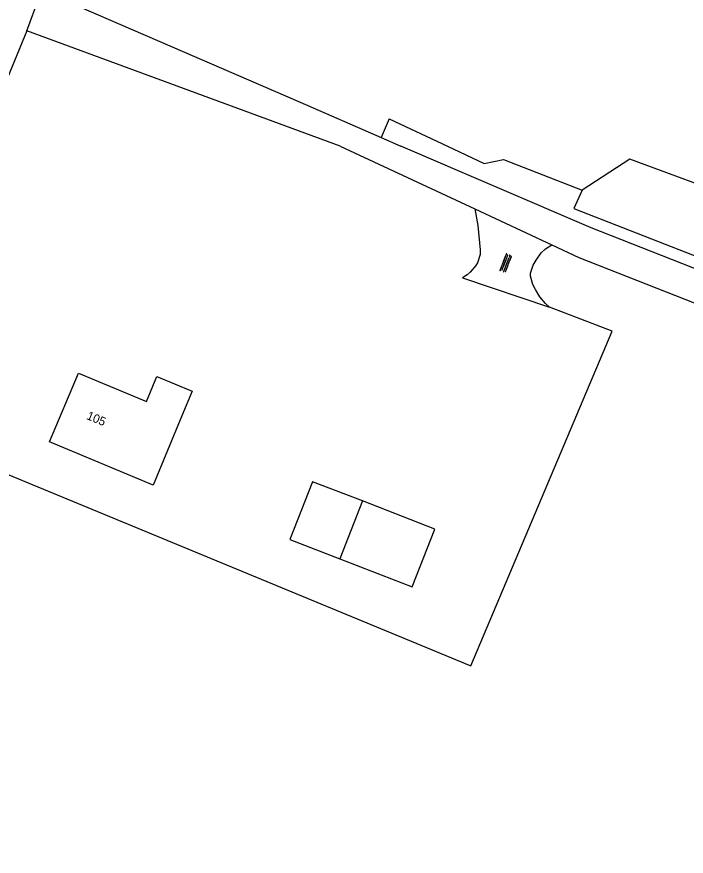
# Model space of a CAD drawing. Extents: x 130998 to 133001, y 398999 to 403002.
# Drawn here: x 131386.2 to 131463.7, y 400917.8 to 401015 of the extents above; entities that cross this region are included whole.
import ezdxf

# ---------------------------------------------------------------- set-up
doc = ezdxf.new("R2010")
doc.units = 0
for name, color, linetype in [('gg-afsc-hekwerk', 7, 'Continuous'), ('gg-anno-huisnummerreeks BGT', 7, 'Continuous'), ('gg-bbg-bijgebouw', 7, 'Continuous'), ('gg-bbg-hoofdgebouw', 7, 'Continuous'), ('gg-bbg-open loods', 7, 'Continuous'), ('gg-knt-onverhard', 7, 'Continuous'), ('gt-grn-groengrens', 7, 'Continuous'), ('gt-grn-weggrens', 7, 'Continuous'), ('gt-symb-overige verharding', 7, 'Continuous')]:
    doc.layers.add(name, color=color, linetype=linetype)

# ---------------------------------------------------------------- blocks, each defined once
blk = doc.blocks.new('gt0-OVH')
at = {"layer": 'gt-symb-overige verharding'}
for points in [[(-0.972, 0.298), (-0.967, 0.308), (-0.965, 0.319), (-0.966, 0.33), (-0.971, 0.34), (-0.978, 0.348), (-0.988, 0.353), (-0.999, 0.355), (-1.01, 0.354), (-1.02, 0.349), (-1.028, 0.342), (-1.033, 0.332), (-1.035, 0.321), (-1.034, 0.31), (-1.029, 0.3), (-1.022, 0.292), (-1.012, 0.287), (-1.001, 0.285), (-0.99, 0.286), (-0.98, 0.291)], [(-0.872, 0.106), (-0.867, 0.116), (-0.865, 0.126), (-0.866, 0.137), (-0.871, 0.147), (-0.878, 0.156), (-0.888, 0.161), (-0.899, 0.163), (-0.91, 0.162), (-0.92, 0.157), (-0.928, 0.15), (-0.933, 0.14), (-0.935, 0.129), (-0.934, 0.118), (-0.929, 0.108), (-0.922, 0.1), (-0.912, 0.095), (-0.901, 0.092), (-0.89, 0.094), (-0.88, 0.098)], [(-0.772, 0.298), (-0.767, 0.308), (-0.765, 0.319), (-0.766, 0.33), (-0.771, 0.34), (-0.778, 0.348), (-0.788, 0.353), (-0.799, 0.355), (-0.81, 0.354), (-0.82, 0.349), (-0.828, 0.342), (-0.833, 0.332), (-0.835, 0.321), (-0.834, 0.31), (-0.829, 0.3), (-0.822, 0.292), (-0.812, 0.287), (-0.801, 0.285), (-0.79, 0.286), (-0.78, 0.291)], [(-0.672, 0.106), (-0.667, 0.116), (-0.665, 0.126), (-0.666, 0.137), (-0.671, 0.147), (-0.678, 0.156), (-0.688, 0.161), (-0.699, 0.163), (-0.71, 0.162), (-0.72, 0.157), (-0.728, 0.15), (-0.733, 0.14), (-0.735, 0.129), (-0.734, 0.118), (-0.729, 0.108), (-0.722, 0.1), (-0.712, 0.095), (-0.701, 0.092), (-0.69, 0.094), (-0.68, 0.098)], [(-0.572, 0.298), (-0.567, 0.308), (-0.565, 0.319), (-0.566, 0.33), (-0.571, 0.34), (-0.578, 0.348), (-0.588, 0.353), (-0.599, 0.355), (-0.61, 0.354), (-0.62, 0.349), (-0.628, 0.342), (-0.633, 0.332), (-0.635, 0.321), (-0.634, 0.31), (-0.629, 0.3), (-0.622, 0.292), (-0.612, 0.287), (-0.601, 0.285), (-0.59, 0.286), (-0.58, 0.291)], [(-0.472, 0.106), (-0.467, 0.116), (-0.465, 0.126), (-0.466, 0.137), (-0.471, 0.147), (-0.478, 0.156), (-0.488, 0.161), (-0.499, 0.163), (-0.51, 0.162), (-0.52, 0.157), (-0.528, 0.15), (-0.533, 0.14), (-0.535, 0.129), (-0.534, 0.118), (-0.529, 0.108), (-0.522, 0.1), (-0.512, 0.095), (-0.501, 0.092), (-0.49, 0.094), (-0.48, 0.098)], [(-0.372, 0.298), (-0.367, 0.308), (-0.365, 0.319), (-0.366, 0.33), (-0.371, 0.34), (-0.378, 0.348), (-0.388, 0.353), (-0.399, 0.355), (-0.41, 0.354), (-0.42, 0.349), (-0.428, 0.342), (-0.433, 0.332), (-0.435, 0.321), (-0.434, 0.31), (-0.429, 0.3), (-0.422, 0.292), (-0.412, 0.287), (-0.401, 0.285), (-0.39, 0.286), (-0.38, 0.291)], [(-0.272, 0.106), (-0.267, 0.116), (-0.265, 0.126), (-0.266, 0.137), (-0.271, 0.147), (-0.278, 0.156), (-0.288, 0.161), (-0.299, 0.163), (-0.31, 0.162), (-0.32, 0.157), (-0.328, 0.15), (-0.333, 0.14), (-0.335, 0.129), (-0.334, 0.118), (-0.329, 0.108), (-0.322, 0.1), (-0.312, 0.095), (-0.301, 0.092), (-0.29, 0.094), (-0.28, 0.098)], [(-0.172, 0.298), (-0.167, 0.308), (-0.165, 0.319), (-0.166, 0.33), (-0.171, 0.34), (-0.178, 0.348), (-0.188, 0.353), (-0.199, 0.355), (-0.21, 0.354), (-0.22, 0.349), (-0.228, 0.342), (-0.233, 0.332), (-0.235, 0.321), (-0.234, 0.31), (-0.229, 0.3), (-0.222, 0.292), (-0.212, 0.287), (-0.201, 0.285), (-0.19, 0.286), (-0.18, 0.291)], [(-0.072, 0.106), (-0.067, 0.116), (-0.065, 0.126), (-0.066, 0.137), (-0.071, 0.147), (-0.078, 0.156), (-0.088, 0.161), (-0.099, 0.163), (-0.11, 0.162), (-0.12, 0.157), (-0.128, 0.15), (-0.133, 0.14), (-0.135, 0.129), (-0.134, 0.118), (-0.129, 0.108), (-0.122, 0.1), (-0.112, 0.095), (-0.101, 0.092), (-0.09, 0.094), (-0.08, 0.098)], [(0.028, 0.298), (0.033, 0.308), (0.035, 0.319), (0.034, 0.33), (0.029, 0.34), (0.022, 0.348), (0.012, 0.353), (0.001, 0.355), (-0.01, 0.354), (-0.02, 0.349), (-0.028, 0.342), (-0.033, 0.332), (-0.035, 0.321), (-0.034, 0.31), (-0.029, 0.3), (-0.022, 0.292), (-0.012, 0.287), (-0.001, 0.285), (0.01, 0.286), (0.02, 0.291)], [(0.128, 0.106), (0.133, 0.116), (0.135, 0.126), (0.134, 0.137), (0.129, 0.147), (0.122, 0.156), (0.112, 0.161), (0.101, 0.163), (0.09, 0.162), (0.08, 0.157), (0.072, 0.15), (0.067, 0.14), (0.065, 0.129), (0.066, 0.118), (0.071, 0.108), (0.078, 0.1), (0.088, 0.095), (0.099, 0.092), (0.11, 0.094), (0.12, 0.098)], [(0.228, 0.298), (0.233, 0.308), (0.235, 0.319), (0.234, 0.33), (0.229, 0.34), (0.222, 0.348), (0.212, 0.353), (0.201, 0.355), (0.19, 0.354), (0.18, 0.349), (0.172, 0.342), (0.167, 0.332), (0.165, 0.321), (0.166, 0.31), (0.171, 0.3), (0.178, 0.292), (0.188, 0.287), (0.199, 0.285), (0.21, 0.286), (0.22, 0.291)], [(0.328, 0.106), (0.333, 0.116), (0.335, 0.126), (0.334, 0.137), (0.329, 0.147), (0.322, 0.156), (0.312, 0.161), (0.301, 0.163), (0.29, 0.162), (0.28, 0.157), (0.272, 0.15), (0.267, 0.14), (0.265, 0.129), (0.266, 0.118), (0.271, 0.108), (0.278, 0.1), (0.288, 0.095), (0.299, 0.092), (0.31, 0.094), (0.32, 0.098)], [(0.428, 0.298), (0.433, 0.308), (0.435, 0.319), (0.434, 0.33), (0.429, 0.34), (0.422, 0.348), (0.412, 0.353), (0.401, 0.355), (0.39, 0.354), (0.38, 0.349), (0.372, 0.342), (0.367, 0.332), (0.365, 0.321), (0.366, 0.31), (0.371, 0.3), (0.378, 0.292), (0.388, 0.287), (0.399, 0.285), (0.41, 0.286), (0.42, 0.291)], [(0.528, 0.106), (0.533, 0.116), (0.535, 0.126), (0.534, 0.137), (0.529, 0.147), (0.522, 0.156), (0.512, 0.161), (0.501, 0.163), (0.49, 0.162), (0.48, 0.157), (0.472, 0.15), (0.467, 0.14), (0.465, 0.129), (0.466, 0.118), (0.471, 0.108), (0.478, 0.1), (0.488, 0.095), (0.499, 0.092), (0.51, 0.094), (0.52, 0.098)], [(0.628, 0.298), (0.633, 0.308), (0.635, 0.319), (0.634, 0.33), (0.629, 0.34), (0.622, 0.348), (0.612, 0.353), (0.601, 0.355), (0.59, 0.354), (0.58, 0.349), (0.572, 0.342), (0.567, 0.332), (0.565, 0.321), (0.566, 0.31), (0.571, 0.3), (0.578, 0.292), (0.588, 0.287), (0.599, 0.285), (0.61, 0.286), (0.62, 0.291)], [(0.728, 0.106), (0.733, 0.116), (0.735, 0.126), (0.734, 0.137), (0.729, 0.147), (0.722, 0.156), (0.712, 0.161), (0.701, 0.163), (0.69, 0.162), (0.68, 0.157), (0.672, 0.15), (0.667, 0.14), (0.665, 0.129), (0.666, 0.118), (0.671, 0.108), (0.678, 0.1), (0.688, 0.095), (0.699, 0.092), (0.71, 0.094), (0.72, 0.098)], [(0.828, 0.298), (0.833, 0.308), (0.835, 0.319), (0.834, 0.33), (0.829, 0.34), (0.822, 0.348), (0.812, 0.353), (0.801, 0.355), (0.79, 0.354), (0.78, 0.349), (0.772, 0.342), (0.767, 0.332), (0.765, 0.321), (0.766, 0.31), (0.771, 0.3), (0.778, 0.292), (0.788, 0.287), (0.799, 0.285), (0.81, 0.286), (0.82, 0.291)], [(0.928, 0.106), (0.933, 0.116), (0.935, 0.126), (0.934, 0.137), (0.929, 0.147), (0.922, 0.156), (0.912, 0.161), (0.901, 0.163), (0.89, 0.162), (0.88, 0.157), (0.872, 0.15), (0.867, 0.14), (0.865, 0.129), (0.866, 0.118), (0.871, 0.108), (0.878, 0.1), (0.888, 0.095), (0.899, 0.092), (0.91, 0.094), (0.92, 0.098)], [(1.028, 0.298), (1.033, 0.308), (1.035, 0.319), (1.034, 0.33), (1.029, 0.34), (1.022, 0.348), (1.012, 0.353), (1.001, 0.355), (0.99, 0.354), (0.98, 0.349), (0.972, 0.342), (0.967, 0.332), (0.965, 0.321), (0.966, 0.31), (0.971, 0.3), (0.978, 0.292), (0.988, 0.287), (0.999, 0.285), (1.01, 0.286), (1.02, 0.291)], [(-0.972, -0.142), (-0.967, -0.132), (-0.965, -0.121), (-0.966, -0.11), (-0.971, -0.1), (-0.978, -0.092), (-0.988, -0.087), (-0.999, -0.085), (-1.01, -0.086), (-1.02, -0.091), (-1.028, -0.098), (-1.033, -0.108), (-1.035, -0.119), (-1.034, -0.13), (-1.029, -0.14), (-1.022, -0.148), (-1.012, -0.153), (-1.001, -0.155), (-0.99, -0.154), (-0.98, -0.149)], [(-0.872, -0.334), (-0.867, -0.324), (-0.865, -0.314), (-0.866, -0.303), (-0.871, -0.293), (-0.878, -0.284), (-0.888, -0.279), (-0.899, -0.277), (-0.91, -0.278), (-0.92, -0.283), (-0.928, -0.29), (-0.933, -0.3), (-0.935, -0.311), (-0.934, -0.322), (-0.929, -0.332), (-0.922, -0.34), (-0.912, -0.345), (-0.901, -0.348), (-0.89, -0.346), (-0.88, -0.342)], [(-0.772, -0.142), (-0.767, -0.132), (-0.765, -0.121), (-0.766, -0.11), (-0.771, -0.1), (-0.778, -0.092), (-0.788, -0.087), (-0.799, -0.085), (-0.81, -0.086), (-0.82, -0.091), (-0.828, -0.098), (-0.833, -0.108), (-0.835, -0.119), (-0.834, -0.13), (-0.829, -0.14), (-0.822, -0.148), (-0.812, -0.153), (-0.801, -0.155), (-0.79, -0.154), (-0.78, -0.149)], [(-0.672, -0.334), (-0.667, -0.324), (-0.665, -0.314), (-0.666, -0.303), (-0.671, -0.293), (-0.678, -0.284), (-0.688, -0.279), (-0.699, -0.277), (-0.71, -0.278), (-0.72, -0.283), (-0.728, -0.29), (-0.733, -0.3), (-0.735, -0.311), (-0.734, -0.322), (-0.729, -0.332), (-0.722, -0.34), (-0.712, -0.345), (-0.701, -0.348), (-0.69, -0.346), (-0.68, -0.342)], [(-0.572, -0.142), (-0.567, -0.132), (-0.565, -0.121), (-0.566, -0.11), (-0.571, -0.1), (-0.578, -0.092), (-0.588, -0.087), (-0.599, -0.085), (-0.61, -0.086), (-0.62, -0.091), (-0.628, -0.098), (-0.633, -0.108), (-0.635, -0.119), (-0.634, -0.13), (-0.629, -0.14), (-0.622, -0.148), (-0.612, -0.153), (-0.601, -0.155), (-0.59, -0.154), (-0.58, -0.149)], [(-0.472, -0.334), (-0.467, -0.324), (-0.465, -0.314), (-0.466, -0.303), (-0.471, -0.293), (-0.478, -0.284), (-0.488, -0.279), (-0.499, -0.277), (-0.51, -0.278), (-0.52, -0.283), (-0.528, -0.29), (-0.533, -0.3), (-0.535, -0.311), (-0.534, -0.322), (-0.529, -0.332), (-0.522, -0.34), (-0.512, -0.345), (-0.501, -0.348), (-0.49, -0.346), (-0.48, -0.342)], [(-0.372, -0.142), (-0.367, -0.132), (-0.365, -0.121), (-0.366, -0.11), (-0.371, -0.1), (-0.378, -0.092), (-0.388, -0.087), (-0.399, -0.085), (-0.41, -0.086), (-0.42, -0.091), (-0.428, -0.098), (-0.433, -0.108), (-0.435, -0.119), (-0.434, -0.13), (-0.429, -0.14), (-0.422, -0.148), (-0.412, -0.153), (-0.401, -0.155), (-0.39, -0.154), (-0.38, -0.149)], [(-0.272, -0.334), (-0.267, -0.324), (-0.265, -0.314), (-0.266, -0.303), (-0.271, -0.293), (-0.278, -0.284), (-0.288, -0.279), (-0.299, -0.277), (-0.31, -0.278), (-0.32, -0.283), (-0.328, -0.29), (-0.333, -0.3), (-0.335, -0.311), (-0.334, -0.322), (-0.329, -0.332), (-0.322, -0.34), (-0.312, -0.345), (-0.301, -0.348), (-0.29, -0.346), (-0.28, -0.342)], [(-0.172, -0.142), (-0.167, -0.132), (-0.165, -0.121), (-0.166, -0.11), (-0.171, -0.1), (-0.178, -0.092), (-0.188, -0.087), (-0.199, -0.085), (-0.21, -0.086), (-0.22, -0.091), (-0.228, -0.098), (-0.233, -0.108), (-0.235, -0.119), (-0.234, -0.13), (-0.229, -0.14), (-0.222, -0.148), (-0.212, -0.153), (-0.201, -0.155), (-0.19, -0.154), (-0.18, -0.149)], [(-0.072, -0.334), (-0.067, -0.324), (-0.065, -0.314), (-0.066, -0.303), (-0.071, -0.293), (-0.078, -0.284), (-0.088, -0.279), (-0.099, -0.277), (-0.11, -0.278), (-0.12, -0.283), (-0.128, -0.29), (-0.133, -0.3), (-0.135, -0.311), (-0.134, -0.322), (-0.129, -0.332), (-0.122, -0.34), (-0.112, -0.345), (-0.101, -0.348), (-0.09, -0.346), (-0.08, -0.342)], [(0.028, -0.142), (0.033, -0.132), (0.035, -0.121), (0.034, -0.11), (0.029, -0.1), (0.022, -0.092), (0.012, -0.087), (0.001, -0.085), (-0.01, -0.086), (-0.02, -0.091), (-0.028, -0.098), (-0.033, -0.108), (-0.035, -0.119), (-0.034, -0.13), (-0.029, -0.14), (-0.022, -0.148), (-0.012, -0.153), (-0.001, -0.155), (0.01, -0.154), (0.02, -0.149)], [(0.128, -0.334), (0.133, -0.324), (0.135, -0.314), (0.134, -0.303), (0.129, -0.293), (0.122, -0.284), (0.112, -0.279), (0.101, -0.277), (0.09, -0.278), (0.08, -0.283), (0.072, -0.29), (0.067, -0.3), (0.065, -0.311), (0.066, -0.322), (0.071, -0.332), (0.078, -0.34), (0.088, -0.345), (0.099, -0.348), (0.11, -0.346), (0.12, -0.342)], [(0.228, -0.142), (0.233, -0.132), (0.235, -0.121), (0.234, -0.11), (0.229, -0.1), (0.222, -0.092), (0.212, -0.087), (0.201, -0.085), (0.19, -0.086), (0.18, -0.091), (0.172, -0.098), (0.167, -0.108), (0.165, -0.119), (0.166, -0.13), (0.171, -0.14), (0.178, -0.148), (0.188, -0.153), (0.199, -0.155), (0.21, -0.154), (0.22, -0.149)], [(0.328, -0.334), (0.333, -0.324), (0.335, -0.314), (0.334, -0.303), (0.329, -0.293), (0.322, -0.284), (0.312, -0.279), (0.301, -0.277), (0.29, -0.278), (0.28, -0.283), (0.272, -0.29), (0.267, -0.3), (0.265, -0.311), (0.266, -0.322), (0.271, -0.332), (0.278, -0.34), (0.288, -0.345), (0.299, -0.348), (0.31, -0.346), (0.32, -0.342)], [(0.428, -0.142), (0.433, -0.132), (0.435, -0.121), (0.434, -0.11), (0.429, -0.1), (0.422, -0.092), (0.412, -0.087), (0.401, -0.085), (0.39, -0.086), (0.38, -0.091), (0.372, -0.098), (0.367, -0.108), (0.365, -0.119), (0.366, -0.13), (0.371, -0.14), (0.378, -0.148), (0.388, -0.153), (0.399, -0.155), (0.41, -0.154), (0.42, -0.149)], [(0.528, -0.334), (0.533, -0.324), (0.535, -0.314), (0.534, -0.303), (0.529, -0.293), (0.522, -0.284), (0.512, -0.279), (0.501, -0.277), (0.49, -0.278), (0.48, -0.283), (0.472, -0.29), (0.467, -0.3), (0.465, -0.311), (0.466, -0.322), (0.471, -0.332), (0.478, -0.34), (0.488, -0.345), (0.499, -0.348), (0.51, -0.346), (0.52, -0.342)], [(0.628, -0.142), (0.633, -0.132), (0.635, -0.121), (0.634, -0.11), (0.629, -0.1), (0.622, -0.092), (0.612, -0.087), (0.601, -0.085), (0.59, -0.086), (0.58, -0.091), (0.572, -0.098), (0.567, -0.108), (0.565, -0.119), (0.566, -0.13), (0.571, -0.14), (0.578, -0.148), (0.588, -0.153), (0.599, -0.155), (0.61, -0.154), (0.62, -0.149)], [(0.728, -0.334), (0.733, -0.324), (0.735, -0.314), (0.734, -0.303), (0.729, -0.293), (0.722, -0.284), (0.712, -0.279), (0.701, -0.277), (0.69, -0.278), (0.68, -0.283), (0.672, -0.29), (0.667, -0.3), (0.665, -0.311), (0.666, -0.322), (0.671, -0.332), (0.678, -0.34), (0.688, -0.345), (0.699, -0.348), (0.71, -0.346), (0.72, -0.342)], [(0.828, -0.142), (0.833, -0.132), (0.835, -0.121), (0.834, -0.11), (0.829, -0.1), (0.822, -0.092), (0.812, -0.087), (0.801, -0.085), (0.79, -0.086), (0.78, -0.091), (0.772, -0.098), (0.767, -0.108), (0.765, -0.119), (0.766, -0.13), (0.771, -0.14), (0.778, -0.148), (0.788, -0.153), (0.799, -0.155), (0.81, -0.154), (0.82, -0.149)], [(0.928, -0.334), (0.933, -0.324), (0.935, -0.314), (0.934, -0.303), (0.929, -0.293), (0.922, -0.284), (0.912, -0.279), (0.901, -0.277), (0.89, -0.278), (0.88, -0.283), (0.872, -0.29), (0.867, -0.3), (0.865, -0.311), (0.866, -0.322), (0.871, -0.332), (0.878, -0.34), (0.888, -0.345), (0.899, -0.348), (0.91, -0.346), (0.92, -0.342)], [(1.028, -0.142), (1.033, -0.132), (1.035, -0.121), (1.034, -0.11), (1.029, -0.1), (1.022, -0.092), (1.012, -0.087), (1.001, -0.085), (0.99, -0.086), (0.98, -0.091), (0.972, -0.098), (0.967, -0.108), (0.965, -0.119), (0.966, -0.13), (0.971, -0.14), (0.978, -0.148), (0.988, -0.153), (0.999, -0.155), (1.01, -0.154), (1.02, -0.149)]]:
    blk.add_lwpolyline(points, close=True, dxfattribs=at)

msp = doc.modelspace()

# ---------------------------------------------------------------- linework, layer by layer
at = {"layer": 'gg-afsc-hekwerk'}
msp.add_line((131429.3, 401003.147), (131436.017, 401000), dxfattribs=at)
for points in [[(131436.017, 401000), (131440.284, 400998.001), (131442.511, 400998.452), (131451.632, 400994.884)], [(131451.632, 400994.884), (131450.632, 400992.78), (131466.85, 400986.437), (131509.92, 400969.213), (131574.152, 400943.97), (131609.926, 400929.573), (131633.504, 400920.444)]]:
    msp.add_lwpolyline(points, dxfattribs=at)
at = {"layer": 'gg-bbg-bijgebouw'}
msp.add_line((131426.186, 400958.916), (131423.577, 400952.195), dxfattribs=at)
msp.add_lwpolyline([(131426.186, 400958.916), (131420.43, 400961.139), (131417.794, 400954.44), (131423.577, 400952.195)], dxfattribs=at)
at = {"layer": 'gg-bbg-hoofdgebouw'}
msp.add_line((131390, 400965.74), (131393.33, 400973.69), dxfattribs=at)
msp.add_lwpolyline([(131393.33, 400973.69), (131401.226, 400970.44), (131402.407, 400973.308), (131406.482, 400971.629), (131405.301, 400968.76), (131405.312, 400968.755), (131401.976, 400960.749), (131390, 400965.74)], dxfattribs=at)
at = {"layer": 'gg-bbg-open loods'}
msp.add_lwpolyline([(131423.577, 400952.195), (131431.939, 400948.95), (131434.575, 400955.649), (131426.186, 400958.916)], dxfattribs=at)
at = {"layer": 'gg-knt-onverhard'}
for p, q in [((131387.37, 401013.351), (131381.864, 401000)), ((131423.622, 401000), (131387.37, 401013.351)), ((131428.356, 401000.998), (131430.629, 401000)), ((131423.622, 401000), (131439.18, 400992.731))]:
    msp.add_line(p, q, dxfattribs=at)
for points in [[(131389.1, 401018.054), (131419.008, 401005.103), (131428.356, 401000.998)], [(131744.692, 400874.259), (131710.795, 400887.942), (131665.032, 400906.641), (131611.692, 400927.534), (131580.256, 400940.175), (131543.144, 400954.926), (131452.641, 400990.522), (131430.629, 401000)], [(131439.18, 400992.731), (131439.56, 400990.816), (131439.832, 400988), (131439.811, 400987.442), (131439.497, 400986.492), (131439.301, 400986.16), (131438.651, 400985.397), (131438.301, 400985.101), (131437.753, 400984.761)], [(131447.85, 400981.366), (131447.383, 400981.786), (131446.734, 400982.537), (131446.197, 400983.388), (131445.924, 400983.958), (131445.639, 400984.935), (131445.633, 400985.275), (131445.944, 400986.211), (131446.302, 400986.799), (131446.89, 400987.623), (131447.365, 400988.106), (131448.119, 400988.555)], [(131448.119, 400988.555), (131451.232, 400987.101), (131541.784, 400951.486), (131582.538, 400935.271)]]:
    msp.add_lwpolyline(points, dxfattribs=at)
at = {"layer": 'gt-grn-groengrens'}
msp.add_line((131429.3, 401003.147), (131428.356, 401000.998), dxfattribs=at)
for points in [[(131523.933, 400973.802), (131457.12, 400998.494), (131451.632, 400994.884)], [(131369.022, 400968.66), (131438.741, 400939.824), (131455.066, 400978.568), (131447.85, 400981.366)]]:
    msp.add_lwpolyline(points, dxfattribs=at)
at = {"layer": 'gt-grn-weggrens'}
for p, q in [((131387.37, 401013.351), (131389.1, 401018.054)), ((131439.18, 400992.731), (131448.119, 400988.555)), ((131437.753, 400984.761), (131447.85, 400981.366))]:
    msp.add_line(p, q, dxfattribs=at)

# ---------------------------------------------------------------- block references
at = {"layer": 'gt-symb-overige verharding', "rotation": 68.71983368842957}
msp.add_blockref('gt0-OVH', (131442.783, 400986.452), dxfattribs=at)

# ---------------------------------------------------------------- texts
at = {"layer": 'gg-anno-huisnummerreeks BGT'}
msp.add_text('105', height=1, rotation=337.3, dxfattribs=at).set_placement((131394.193, 400968.414))

doc.saveas('drawing.dxf')
